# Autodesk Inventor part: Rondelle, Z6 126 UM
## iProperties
Created: 2011-12
Part Number: Rondelle, Z6 126 UM
Document SubType Name: Modeling
Designer: A
Manufacturer: Standard
Standards Organization: Custom
Author: A
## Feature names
1. Extrusion1
